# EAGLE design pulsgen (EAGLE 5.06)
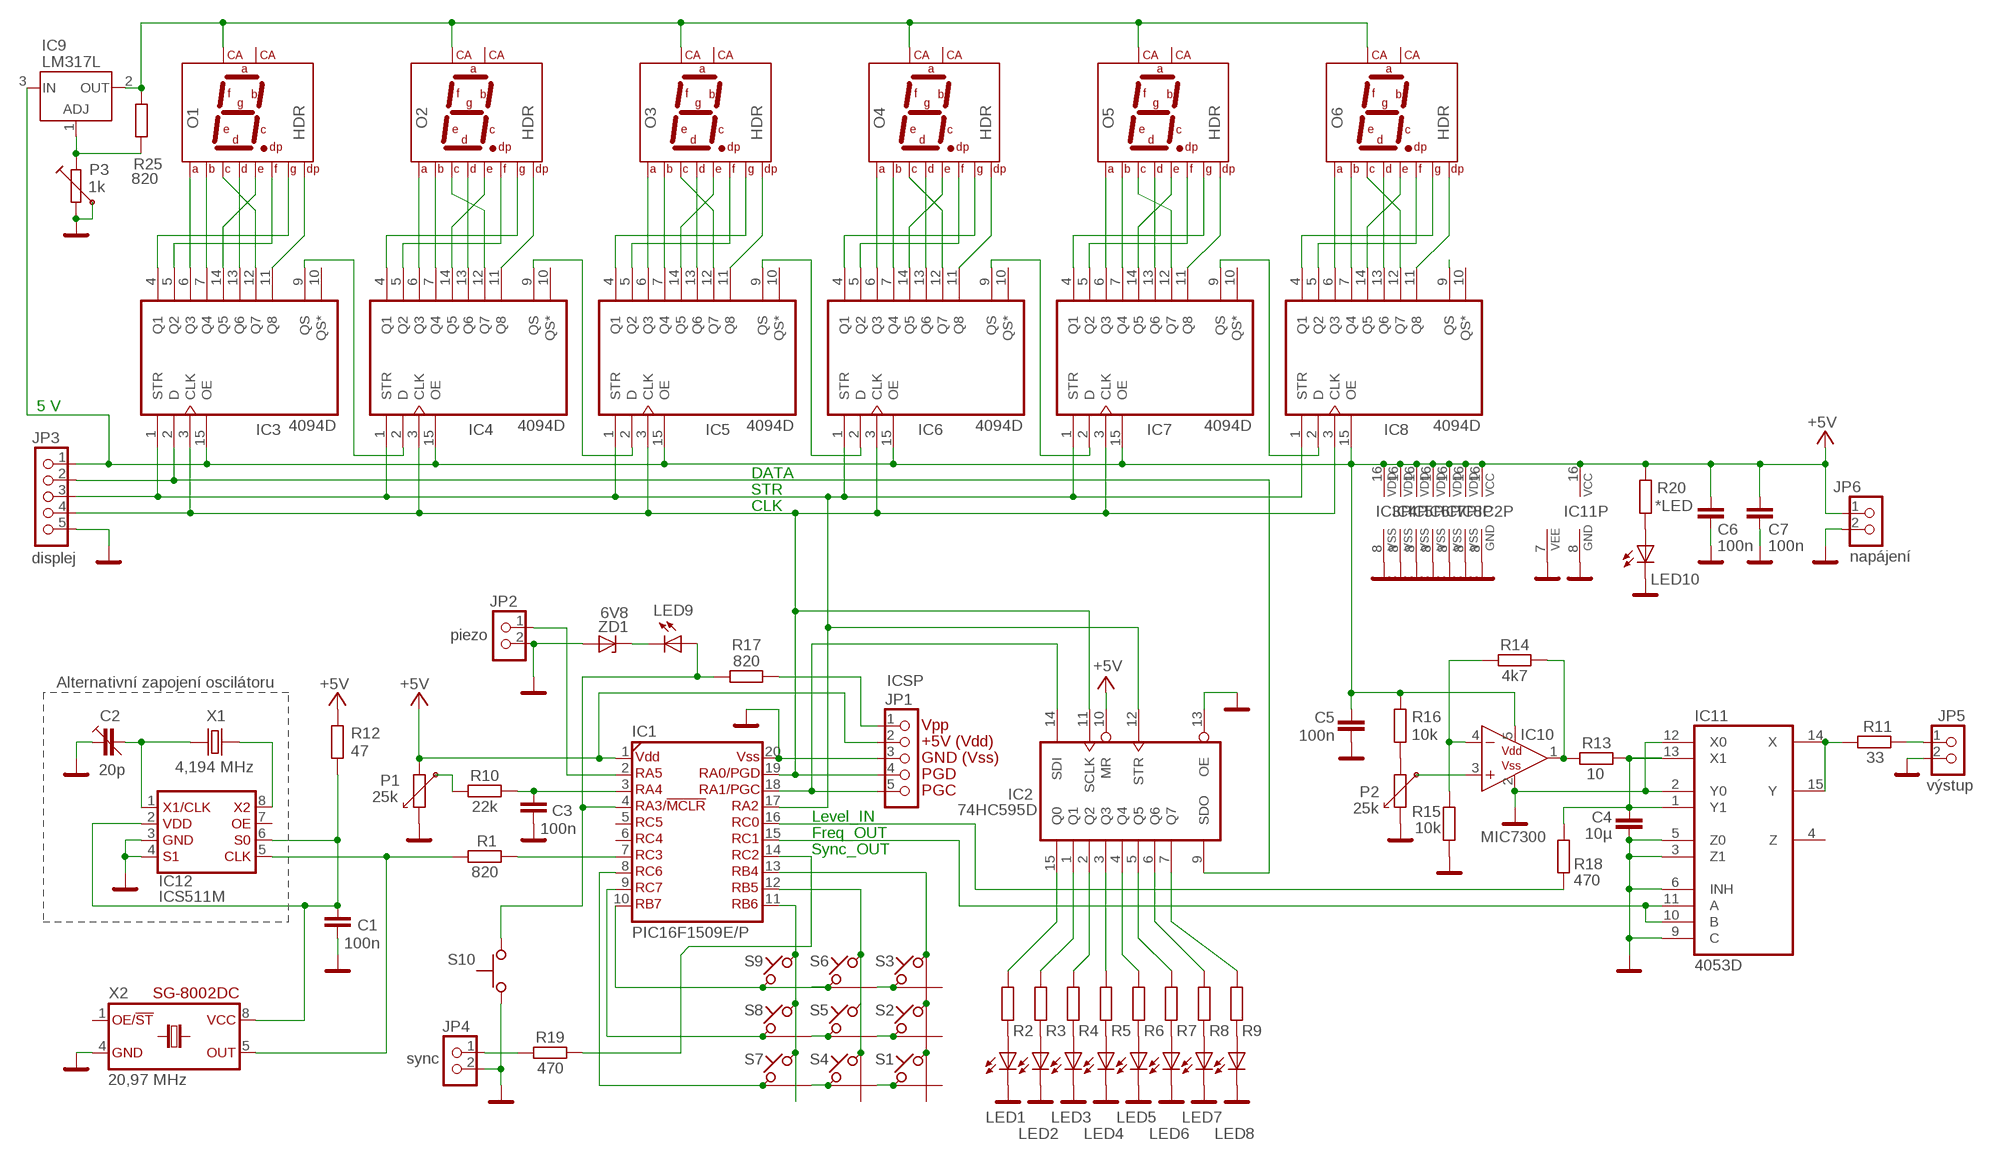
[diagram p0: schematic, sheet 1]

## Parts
C1  100n  CSMD1206_KEMET_REFLOW  [C1206K]
C2  20p  C_TRIMR_JEN_ZNACKA  [2PIN_5MM]
C3  100n  CSMD1206_KEMET_REFLOW  [C1206K]
C4  10µ  CSMD1206_KEMET_REFLOW  [C1206K]
C5  100n  CSMD1206_KEMET_REFLOW  [C1206K]
C6  100n  CSMD1206_KEMET_REFLOW  [C1206K]
C7  100n  CSMD1206_KEMET_REFLOW  [C1206K]
IC1  PIC16F1509E/P  [DIL20]
IC2  74HC595D  74HC595S  [SO16-RN]
IC3  4094D  [SO16-RN]
IC4  4094D  [SO16-RN]
IC5  4094D  [SO16-RN]
IC6  4094D  [SO16-RN]
IC7  4094D  [SO16-RN]
IC8  4094D  [SO16-RN]
IC9  LM317L  [TO92]
IC10  MIC7300  MCP6L01_  [SOT23-5]
IC11  4053D  4053S  [SO16-RN@1]
IC12  ICS511M  ICS511  [SO08-RN]
JP1  ICSP_PIN  [1X05]
JP2  PINHD-1X2  [1X02]
JP3  PINHD-1X5  [1X05]
JP4  PINHD-1X2  [1X02]
JP5  PINHD-1X2  [1X02]
JP6  PINHD-1X2  [1X02]
LED1  LED5MM  [LED5MM]
LED2  LED5MM  [LED5MM]
LED3  LED5MM  [LED5MM]
LED4  LED5MM  [LED5MM]
LED5  LED5MM  [LED5MM]
LED6  LED5MM  [LED5MM]
LED7  LED5MM  [LED5MM]
LED8  LED5MM  [LED5MM]
LED9  LED1206  [SMD1206-LED]
LED10  LED5MM  [LED5MM]
O1  HDR  [HD-A55X]
O2  HDR  [HD-A55X]
O3  HDR  [HD-A55X]
O4  HDR  [HD-A55X]
O5  HDR  [HD-A55X]
O6  HDR  [HD-A55X]
P1  25k  POTENCIOMETR_PC16ML-L  [PC16ML-L]
P2  25k  POTENCIOMETR_PC16ML-L  [PC16ML-L]
P3  1k  R-TRIMRPT6V  [PT6V]
R1  820  REZISTOR_SMD1206_KEMET_REFLOW  [C1206K]
R2  REZISTOR_SMD1206_KEMET_REFLOW  [C1206K]
R3  REZISTOR_SMD1206_KEMET_REFLOW  [C1206K]
R4  REZISTOR_SMD1206_KEMET_REFLOW  [C1206K]
R5  REZISTOR_SMD1206_KEMET_REFLOW  [C1206K]
R6  REZISTOR_SMD1206_KEMET_REFLOW  [C1206K]
R7  REZISTOR_SMD1206_KEMET_REFLOW  [C1206K]
R8  REZISTOR_SMD1206_KEMET_REFLOW  [C1206K]
R9  REZISTOR_SMD1206_KEMET_REFLOW  [C1206K]
R10  22k  REZISTOR_SMD1206_KEMET_REFLOW  [C1206K]
R11  33  REZISTOR_SMD1206_KEMET_REFLOW  [C1206K]
R12  47  REZISTOR_SMD1206_KEMET_REFLOW  [C1206K]
R13  10  REZISTOR_SMD1206_KEMET_REFLOW  [C1206K]
R14  4k7  REZISTOR_SMD1206_KEMET_REFLOW  [C1206K]
R15  10k  REZISTOR_SMD1206_KEMET_REFLOW  [C1206K]
R16  10k  REZISTOR_SMD1206_KEMET_REFLOW  [C1206K]
R17  820  REZISTOR_SMD1206_KEMET_REFLOW  [C1206K]
R18  470  REZISTOR_SMD1206_KEMET_REFLOW  [C1206K]
R19  470  REZISTOR_SMD1206_KEMET_REFLOW  [C1206K]
R20  *LED  REZISTOR_SMD1206_KEMET_REFLOW  [C1206K]
R25  820  REZISTOR_SMD1206_KEMET_REFLOW  [C1206K]
S1  TLACITKO_MATICE_P-B1720  [P-B1720]
S2  TLACITKO_MATICE_P-B1720  [P-B1720]
S3  TLACITKO_MATICE_P-B1720  [P-B1720]
S4  TLACITKO_MATICE_P-B1720  [P-B1720]
S5  TLACITKO_MATICE_P-B1720  [P-B1720]
S6  TLACITKO_MATICE_P-B1720  [P-B1720]
S7  TLACITKO_MATICE_P-B1720  [P-B1720]
S8  TLACITKO_MATICE_P-B1720  [P-B1720]
S9  TLACITKO_MATICE_P-B1720  [P-B1720]
S10  TLACITKOP-B1729  [P-B1729]
X1  4,194 MHz  XTAL_HC49  [XTAL_HC-49]
X2  20,97 MHz  SG-8002DC  [SG-8002DC]
ZD1  6V8  DIODA_ZENER_SOD80  [SOD80-R]

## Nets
+5V: C5.1 C6.1 C7.1 IC1.1(VDD) IC2.10(MR) IC2.16(VCC) IC3.15(OE) IC3.16(VDD) IC4.15(OE) IC4.16(VDD) IC5.15(OE) IC5.16(VDD) IC6.15(OE) IC6.16(VDD) IC7.15(OE) IC7.16(VDD) IC8.15(OE) IC8.16(VDD) IC9.3(IN) IC10.5(VDD) IC11.16(VCC) JP1.2 JP3.1 JP6.1 P1.1 R12.2 R16.1 R20.1
GND: C1.2 C2.P$1 C3.2 C4.2 C5.2 C6.2 C7.2 IC1.20(VSS) IC2.8(GND) IC2.13(OE) IC3.8(VSS) IC4.8(VSS) IC5.8(VSS) IC6.8(VSS) IC7.8(VSS) IC8.8(VSS) IC10.2(VSS) IC11.2(Y0) IC11.3(Z1) IC11.5(Z0) IC11.6(INH) IC11.7(VEE) IC11.8(GND) IC11.9(C) IC11.12(X0) IC12.3(GND) IC12.4(S1) JP1.3 JP2.2 JP3.5 JP4.2 JP5.2 JP6.2 LED1.K(C) LED2.K(C) LED3.K(C) LED4.K(C) LED5.K(C) LED6.K(C) LED7.K(C) LED8.K(C) LED10.K(C) P1.2 P2.2 P3.1 P3.3 R15.2 S10.1 X2.4(GND) ZD1.A
N$1: IC3.4(Q1) O1.10(G)
N$2: IC3.5(Q2) O1.9(F)
N$3: IC3.6(Q3) O1.7(A)
N$4: IC3.7(Q4) O1.6(B)
N$5: IC3.14(Q5) O1.1(E)
N$6: IC3.13(Q6) O1.2(D)
N$7: IC3.12(Q7) O1.4(C)
N$8: IC3.11(Q8) O1.5(DP)
N$9: IC5.4(Q1) O3.10(G)
N$10: IC3.9(QS) IC4.2(D)
N$11: IC9.1(ADJ) P3.2 R25.2
N$12: IC4.9(QS) IC5.2(D)
N$13: IC4.4(Q1) O2.10(G)
N$14: IC4.5(Q2) O2.9(F)
N$15: IC4.6(Q3) O2.7(A)
N$16: IC4.7(Q4) O2.6(B)
N$17: IC4.14(Q5) O2.1(E)
N$18: IC4.13(Q6) O2.2(D)
N$19: IC4.12(Q7) O2.4(C)
N$20: IC4.11(Q8) O2.5(DP)
N$21: LED9.K(C) ZD1.K
N$22: IC1.18(RA1) IC2.14(SDI) JP1.5
N$23: IC8.9(QS)
N$24: IC6.4(Q1) O4.10(G)
N$25: IC6.5(Q2) O4.9(F)
N$26: IC6.6(Q3) O4.7(A)
N$27: IC6.7(Q4) O4.6(B)
N$28: IC6.14(Q5) O4.1(E)
N$29: IC6.13(Q6) O4.2(D)
N$30: IC6.12(Q7) O4.4(C)
N$31: IC6.11(Q8) O4.5(DP)
N$32: IC7.4(Q1) O5.10(G)
N$33: IC5.5(Q2) O3.9(F)
N$34: IC5.6(Q3) O3.7(A)
N$35: IC5.7(Q4) O3.6(B)
N$36: IC5.14(Q5) O3.1(E)
N$37: IC5.13(Q6) O3.2(D)
N$38: IC5.12(Q7) O3.4(C)
N$39: IC5.11(Q8) O3.5(DP)
N$40: IC7.5(Q2) O5.9(F)
N$41: IC2.9(SDO) IC3.2(D) JP3.2
N$42: IC12.5(CLK) R1.1 X2.5(OUT)
N$43: IC1.7(RC3) R1.2
N$44: P1.3 R10.1
N$45: IC7.6(Q3) O5.7(A)
N$46: IC7.7(Q4) O5.6(B)
N$47: IC7.14(Q5) O5.1(E)
N$48: IC7.13(Q6) O5.2(D)
N$49: IC7.12(Q7) O5.4(C)
N$50: IC7.11(Q8) O5.5(DP)
N$51: IC8.4(Q1) O6.10(G)
N$52: IC8.5(Q2) O6.9(F)
N$53: IC8.6(Q3) O6.7(A)
N$54: IC8.7(Q4) O6.6(B)
N$55: IC8.14(Q5) O6.1(E)
N$56: IC8.13(Q6) O6.2(D)
N$57: IC8.12(Q7) O6.4(C)
N$58: IC8.11(Q8) O6.5(DP)
N$59: IC9.2(OUT) O1.3(CA1) O2.3(CA1) O3.3(CA1) O4.3(CA1) O5.3(CA1) O6.3(CA1) R25.1
N$60: JP5.1 R11.2
N$61: C3.1 IC1.3(RA4) R10.2
N$62: IC1.17(RA2) IC2.12(STR) IC3.1(STR) IC4.1(STR) IC5.1(STR) IC6.1(STR) IC7.1(STR) IC8.1(STR) JP3.3
N$63: IC7.9(QS) IC8.2(D)
N$64: IC5.9(QS) IC6.2(D)
N$65: IC1.4(RA3) LED9.A R17.1 S10.2
N$66: IC6.9(QS) IC7.2(D)
N$67: IC12.8(X2) X1.2
N$68: C2.P$2 IC12.1(X1/CLK) X1.1
N$69: S2.2 S3.4
N$70: S1.2 S2.4
N$71: C1.1 IC12.2(VDD) IC12.6(S0) R12.1 X2.8(VCC)
N$72: IC1.10(RB7) S6.1 S9.1 S9.3
N$73: S5.2 S6.4
N$74: S8.2 S9.4
N$75: IC1.9(RC7) S8.1
N$76: IC1.8(RC6) S7.1
N$77: S7.2 S8.4
N$78: IC11.14(X) IC11.15(Y) R11.1
N$79: S3.1 S6.3
N$80: S2.1 S5.3
N$81: IC1.13(RB4) S3.2
N$82: S1.1 S4.3
N$83: JP1.1 R17.2
N$84: S5.1 S8.3
N$85: IC1.11(RB6) S7.4 S9.2
N$86: S4.1 S7.3
N$87: IC10.1(OUT) R13.1 R14.2
N$88: IC2.15(Q0) R2.2
N$89: IC2.1(Q1) R3.2
N$90: IC2.2(Q2) R4.2
N$91: IC2.3(Q3) R5.2
N$92: IC2.4(Q4) R6.2
N$93: IC2.5(Q5) R7.2
N$94: IC2.6(Q6) R8.2
N$95: IC2.7(Q7) R9.2
N$96: LED1.A R2.1
N$97: LED2.A R3.1
N$98: LED3.A R4.1
N$99: LED4.A R5.1
N$100: LED5.A R6.1
N$101: LED6.A R7.1
N$102: LED7.A R8.1
N$103: LED8.A R9.1
N$104: IC1.2(RA5) JP2.1
N$105: P2.1 R16.2
N$106: IC1.15(RC1) IC11.10(B) IC11.11(A)
N$107: IC1.16(RC0) R18.2
N$108: IC1.12(RB5) S4.2 S5.4 S6.2
N$109: IC10.3(+IN) P2.3
N$110: IC10.4(-IN) R14.1 R15.1
N$111: IC1.19(RA0) IC2.11(SCLK) IC3.3(CLK) IC4.3(CLK) IC5.3(CLK) IC6.3(CLK) IC7.3(CLK) IC8.3(CLK) JP1.4 JP3.4
N$115: JP4.1 R19.1
N$116: C4.1 IC11.1(Y1) IC11.13(X1) R13.2 R18.1
N$117: IC1.14(RC2) R19.2
N$118: LED10.A R20.2
Unconnected: IC1.5(RC5) IC1.6(RC4) IC3.10(QS*) IC4.10(QS*) IC5.10(QS*) IC6.10(QS*) IC7.10(QS*) IC8.10(QS*) IC11.4(Z) IC12.7(OE) O1.8(CA2) O2.8(CA2) O3.8(CA2) O4.8(CA2) O5.8(CA2) O6.8(CA2) S1.3 S1.4 S2.3 S3.3 S4.4 S10.3 S10.4 X2.1(OE/!ST)

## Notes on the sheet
- 5 V
- DATA
- STR
- CLK
- displej | napájení
- piezo
- Alternativní zapojení oscilátoru | ICSP
- výstup
- Level_IN
- Freq_OUT
- Sync_OUT
- sync

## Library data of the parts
C1 C3-C7 = #bcs7d:C: Kondenzatory, keramicke a foliove
C2 = #bcs7d:C_TRIMR_JEN_ZNACKA: C trimr jen znacka
IC1 = #bcs-ic1:PIC16F1509
IC2 = 74xx-bcs:74*595: 8-bit SHIFT REGISTER, output latch
IC3-IC8 = 40xx_bcs:4094: 8-stage SHIFT/STORE REGISTER, tri-state
IC9 = #bcs-ic1:LM317L
IC10 = #bcs-ic1:MCP6L01: 5 pin OA MCP6L01
IC11 = 40xx_bcs:4053: Triple 2-channel ANALOG MULTIPLEXER
IC12 = #bcs-ic1:ICS511
JP1 = #bcs-ic1:ICSP_PIN: PIN HEADER
JP2 JP4-JP6 = #bcs_pinhead:PINHD-1X2: PIN HEADER
JP3 = #bcs_pinhead:PINHD-1X5: PIN HEADER
LED1-LED10 = #bcs7d:LED: LED
O1-O6 = #bcs-ic1:HD: 7 segment display
P1 P2 = #bcs7d:POTENCIOMETR
P3 = #bcs7d:R-TRIMR
R1-R20 R25 = #bcs7d:REZISTOR_
S1-S9 = #bcs7d:TLACITKO_MATICE: Tlacitko 4 piny pro maticové klávesnice
S10 = #bcs7d:TLACITKO
X1 = #bcs7d:XTAL
X2 = #bcs-ic1:SG-8002DC: EPSON Programmable oscillator
ZD1 = #bcs7d:DIODA_ZENER

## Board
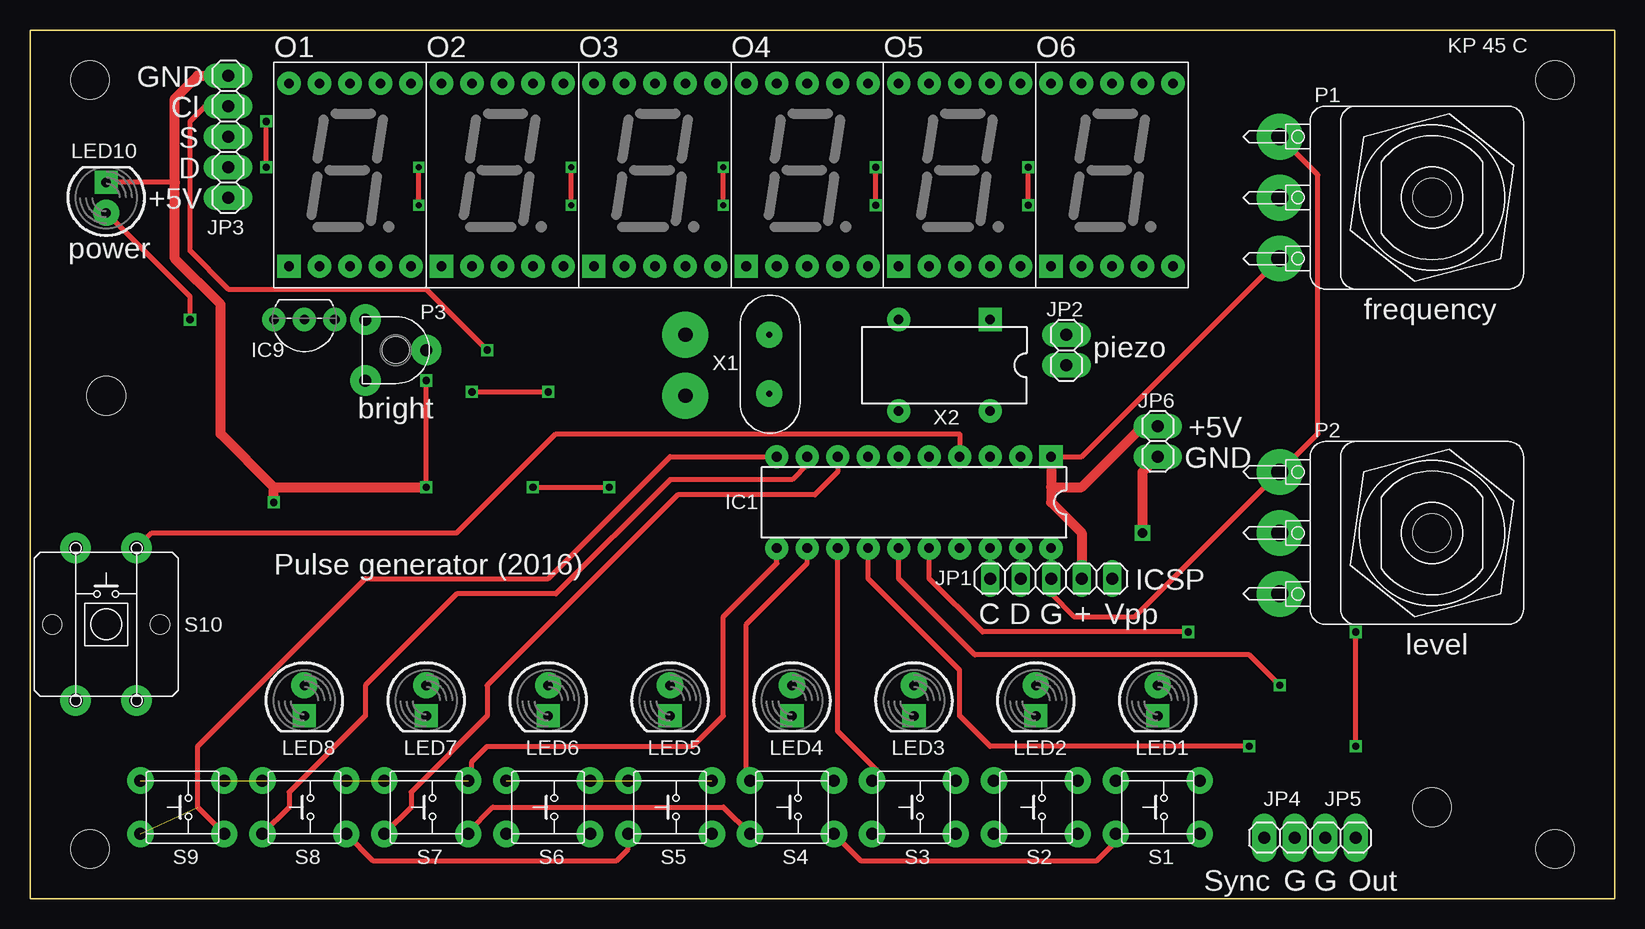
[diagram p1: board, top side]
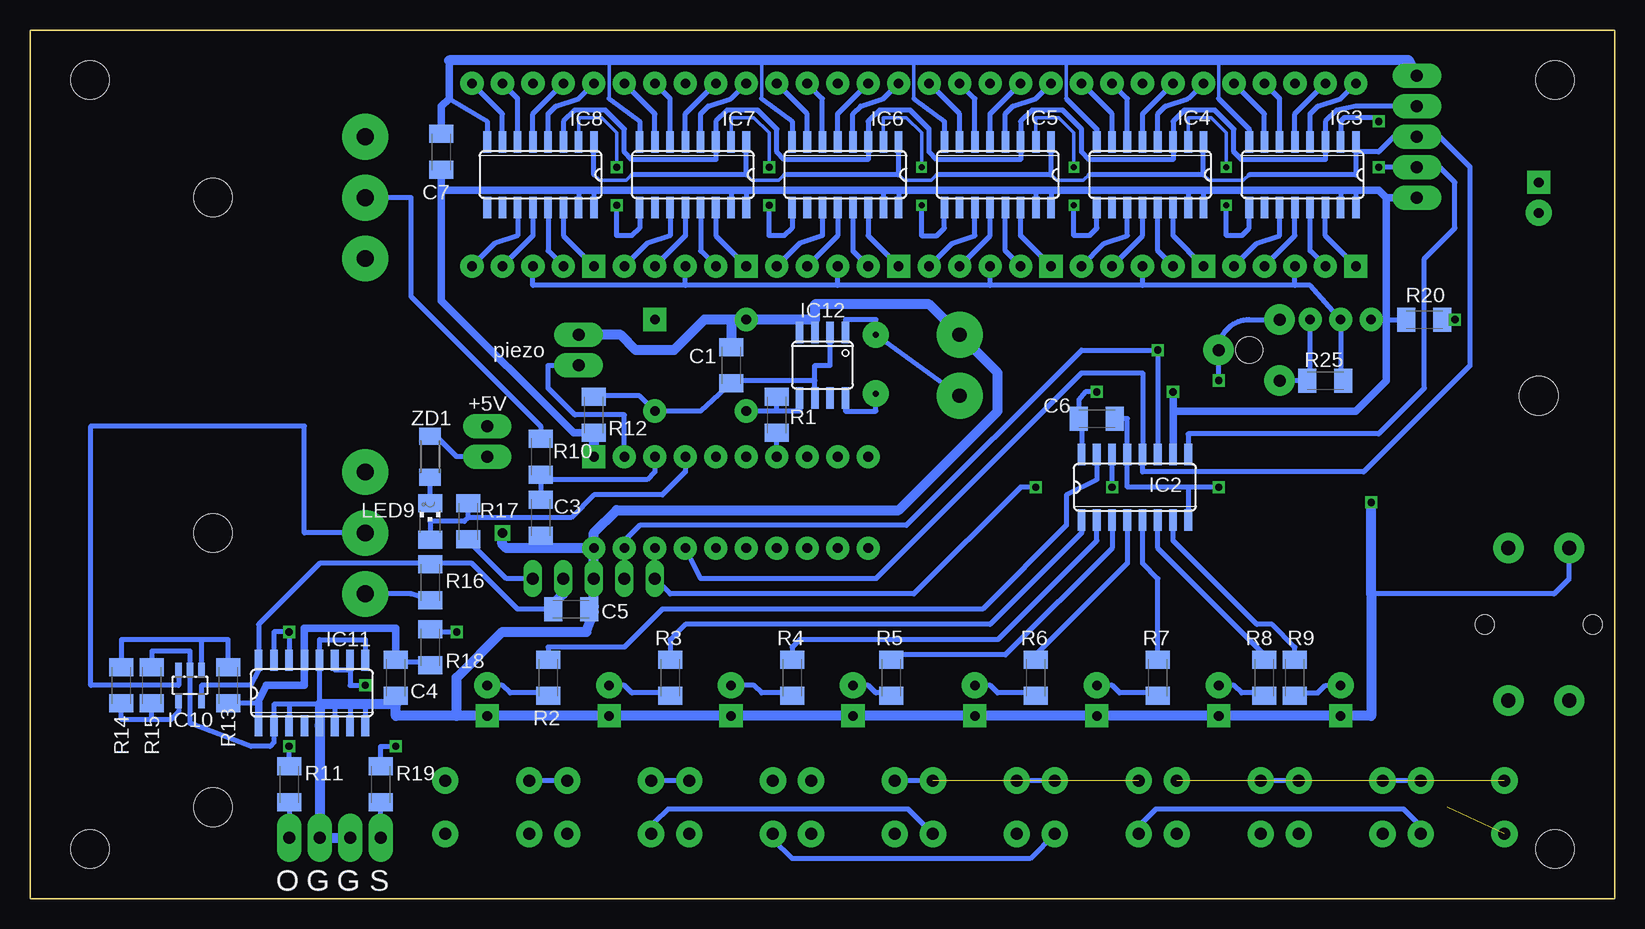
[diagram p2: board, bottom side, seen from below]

Size 132.08 x 72.39 mm. Coordinates in mm from the lower left corner, seen from the top.
Copper layers (1*16): Top 0.035mm / dielectric 1.5mm / Bottom 0.035mm
Design rules "default": minimum track width 10mil, minimum drill 24mil, track to track 8mil, track to pad 8mil, pad to pad 8mil, via to via 8mil, smd to smd 8mil, copper to edge 40mil, drill to drill 8mil, minimum pad ring 10mil, minimum via ring 8mil, stop-mask expansion 4mil, vias tented up to drill 0mil, thermal gap 10mil
Holes 3.2 mm at 116.84,7.62 116.84,30.48 116.84,58.42 6.35,41.91
Holes 2.2 mm at 30.48,45.72

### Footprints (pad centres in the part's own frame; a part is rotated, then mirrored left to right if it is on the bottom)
C1206K = smd 1.5 x 2: 1 -1.5,0; 2 1.5,0
2PIN_5MM = drill 1.2 pad 3.81 round: P$1 -2.54,0; P$2 2.54,0
DIL20 = drill 0.8 pad 1.93 square: 1 -11.43,-3.81 | drill 0.8 pad 1.93 round: 2 -8.89,-3.81; 3 -6.35,-3.81; 4 -3.81,-3.81; 5 -1.27,-3.81; 6 1.27,-3.81; 7 3.81,-3.81; 8 6.35,-3.81; 9 8.89,-3.81; 10 11.43,-3.81; 11 11.43,3.81; 12 8.89,3.81; 13 6.35,3.81; 14 3.81,3.81; 15 1.27,3.81; 16 -1.27,3.81; 17 -3.81,3.81; 18 -6.35,3.81; 19 -8.89,3.81; 20 -11.43,3.81
SO16-RN = smd 0.635 x 1.778: 1 -3.81,-2.731; 2 -2.54,-2.731; 3 -1.27,-2.731; 4 0,-2.731; 5 1.27,-2.731; 6 2.54,-2.731; 7 3.81,-2.731; 8 5.08,-2.731; 9 5.08,2.731; 10 3.81,2.731; 11 2.54,2.731; 12 1.27,2.731; 13 0,2.731; 14 -1.27,2.731; 15 -2.54,2.731; 16 -3.81,2.731
SO16-RN' = smd 0.635 x 1.778: 1 -4.445,-2.731; 2 -3.175,-2.731; 3 -1.905,-2.731; 4 -0.635,-2.731; 5 0.635,-2.731; 6 1.905,-2.731; 7 3.175,-2.731; 8 4.445,-2.731; 9 4.445,2.731; 10 3.175,2.731; 11 1.905,2.731; 12 0.635,2.731; 13 -0.635,2.731; 14 -1.905,2.731; 15 -3.175,2.731; 16 -4.445,2.731
TO92 = drill 0.8 pad 1.93 round: 1 -2.54,0; 2 0,0; 3 2.54,0
SOT23-5 = smd 0.55 x 1.2: 1 -0.95,-1.3; 2 0,-1.3; 3 0.95,-1.3; 4 0.95,1.3; 5 -0.95,1.3
SO16-RN@1 = smd 0.635 x 1.778: 1 -3.81,-2.731; 2 -2.54,-2.731; 3 -1.27,-2.731; 4 0,-2.731; 5 1.27,-2.731; 6 2.54,-2.731; 7 3.81,-2.731; 8 5.08,-2.731; 9 5.08,2.731; 10 3.81,2.731; 11 2.54,2.731; 12 1.27,2.731; 13 0,2.731; 14 -1.27,2.731; 15 -2.54,2.731; 16 -3.81,2.731
SO08-RN = smd 0.635 x 1.778: 1 -1.905,-2.731; 2 -0.635,-2.731; 3 0.635,-2.731; 4 1.905,-2.731; 5 1.905,2.731; 6 0.635,2.731; 7 -0.635,2.731; 8 -1.905,2.731
1X05 = drill 1 pad 1.524 long: 1 -5.08,0; 2 -2.54,0; 3 0,0; 4 2.54,0; 5 5.08,0
1X02 = drill 1 pad 2.032 long: 1 -1.27,0; 2 1.27,0
1X05' = drill 1 pad 2.032 long: 1 -5.08,0; 2 -2.54,0; 3 0,0; 4 2.54,0; 5 5.08,0
LED5MM = drill 0.8 pad 2.184 round: A -1.27,0 | drill 0.8 pad 1.93 square: K 1.27,0
SMD1206-LED = smd 1.5 x 2: A -1.511,0; K 1.511,0
HD-A55X = drill 0.8 pad 1.93 square: 1 0,0 | drill 0.8 pad 1.93 round: 2 2.54,0; 3 5.08,0; 4 7.62,0; 5 10.16,0; 6 10.16,15.24; 7 7.62,15.24; 8 5.08,15.24; 9 2.54,15.24; 10 0,15.24
PC16ML-L = drill 1.4 pad 3.81 round: 1 -5.08,12.7; 2 5.08,12.7; 3 0,12.7
PT6V = drill 1 pad 2.54 round: 1 -2.54,-2.54; 2 2.54,-2.54; 3 0,2.54
P-B1720 = drill 1 pad 2.184 round: 1 -3.493,-2.223; 2 -3.493,2.223; 3 3.493,-2.223; 4 3.493,2.223
P-B1729 = drill 1.2 pad 2.54 round: 1 -6.35,-2.54; 2 -6.35,2.54; 3 6.35,-2.54; 4 6.35,2.54 | hole 1.6: 0,4.5; 0,-4.5
KRABICKA_KP_45_C = hole 3.2: 4.991,4.128; 4.991,68.237; 127.089,68.237; 127.089,4.128
XTAL_HC-49 = drill 0.5 pad 2.184 round: 1 0,0; 2 4.9,0
SG-8002DC = drill 0.8 pad 1.93 square: 1 -3.81,-3.81 | drill 0.8 pad 1.93 round: 4 3.81,-3.81; 5 3.81,3.81; 8 -3.81,3.81
SOD80-R = smd 1.397 x 1.778: A 1.714,0; K -1.714,0

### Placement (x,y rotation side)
C1  73.66,44.45 90 bottom
C2  54.61,44.45 270 top
C3  89.53,31.75 270 bottom
C4  101.6,18.41 270 bottom
C5  87,24.13 0 bottom
C6  43.18,40.01 0 bottom
C7  97.79,62.23 90 bottom
IC1  73.66,33.02 180 top
IC2  40.64,34.29 0 bottom
IC3  4094D  [SO16-RN']  26.04,60.33 180 bottom
IC4  4094D  [SO16-RN']  38.73,60.33 180 bottom
IC5  4094D  [SO16-RN']  51.44,60.33 180 bottom
IC6  4094D  [SO16-RN']  64.14,60.33 180 bottom
IC7  4094D  [SO16-RN']  76.83,60.33 180 bottom
IC8  4094D  [SO16-RN']  89.53,60.33 180 bottom
IC9  22.86,48.26 180 top
IC10  118.75,17.78 180 bottom
IC11  109.22,17.14 0 bottom
IC12  66.04,44.45 180 bottom
JP1  85.09,26.67 180 top
JP2  86.36,45.72 90 top
JP3  [1X05']  16.51,63.5 90 top
JP4  104.14,5.08 0 top
JP5  109.22,5.08 180 top
JP6  93.98,38.1 270 top
LED1  93.98,16.51 270 top
LED2  83.82,16.51 270 top
LED3  73.66,16.51 270 top
LED4  63.5,16.51 270 top
LED5  53.34,16.51 270 top
LED6  43.18,16.51 270 top
LED7  33.02,16.51 270 top
LED8  22.86,16.51 270 top
LED9  98.74,31.43 90 bottom
LED10  6.35,58.42 90 top
O1  21.59,52.7 0 top
O2  34.29,52.7 0 top
O3  46.99,52.7 0 top
O4  59.69,52.7 0 top
O5  72.39,52.7 0 top
O6  85.09,52.7 0 top
P1  116.84,58.42 90 top
P2  116.84,30.48 90 top
P3  30.48,45.72 270 top
R1  69.85,40.32 270 bottom
R2  88.9,18.41 90 bottom
R3  78.74,18.41 90 bottom
R4  68.58,18.41 90 bottom
R5  60.33,18.41 90 bottom
R6  48.26,18.41 90 bottom
R7  38.1,18.41 90 bottom
R8  29.21,18.41 90 bottom
R9  26.67,18.41 90 bottom
R10  89.53,36.83 270 bottom
R11  110.49,9.53 270 bottom
R12  85.09,40.32 270 bottom
R13  115.57,17.78 270 bottom
R14  124.46,17.78 90 bottom
R15  121.92,17.78 90 bottom
R16  98.74,26.35 270 bottom
R17  95.57,31.43 270 bottom
R18  98.74,20.95 90 bottom
R19  102.87,9.53 90 bottom
R20  15.88,48.26 0 bottom
R25  24.13,43.18 180 bottom
S1  93.98,7.62 0 top
S2  83.82,7.62 0 top
S3  73.66,7.62 0 top
S4  63.5,7.62 0 top
S5  53.34,7.62 0 top
S6  43.18,7.62 0 top
S7  33.02,7.62 0 top
S8  22.86,7.62 0 top
S9  12.7,7.62 0 top
S10  6.35,22.86 270 top
U$1  [KRABICKA_KP_45_C]  0,0 0 top
X1  61.59,46.99 270 top
X2  76.2,44.45 180 top
ZD1  98.74,36.83 90 bottom

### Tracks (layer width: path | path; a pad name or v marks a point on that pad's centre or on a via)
+5V  (via drill 0.6)
  Top 0.406: v36.83,42.23 v43.18,42.23 | P1.1 87.63,36.83 IC1.1
  Top 0.813: JP1.2 87.63,30.48 85.09,33.02 85.09,34.29 | IC1.1 85.09,34.29 | JP6.1 92.71,39.37 87.63,34.29 85.09,34.29
  Bottom 0.406: 34.29,59.05 IC4.16 | 35.56,59.05 IC4.15 | 46.99,59.05 IC5.16 | 48.26,59.05 IC5.15 | 59.69,59.05 IC6.16 | 86.36,59.05 IC8.15 | 60.96,59.05 IC6.15 | 72.39,59.05 IC7.16 | 73.66,59.05 IC7.15 | 85.09,59.05 IC8.16 | IC10.5 117.8,17.78 113.67,17.78 113.03,19.05 IC11.16 113.03,22.86 107.95,27.94 99.06,27.94 | 99.06,27.94 R16.1 | 99.06,27.94 95.25,27.94 91.44,24.13 C5.1 88.27,24.36 88.27,24.77 | IC2.16 44.45,40.01 C6.1 44.68,41.59 44.13,42.23 v43.18,42.23 | 19.05,48.26 R20.1 | 21.59,59.05 IC3.16 | 22.86,59.05 IC3.15
  Bottom 0.61: 97.79,59.05 86.36,59.05 85.09,59.05 73.66,59.05 72.39,59.05 60.96,59.05 59.69,59.05 48.26,59.05 46.99,59.05 35.56,59.05 34.29,59.05 22.86,59.05 21.59,59.05 19.68,59.05 19.05,58.42 | 36.83,40.64 IC2.10 | 97.79,59.05 97.79,49.85 86.77,38.82 R12.2 | 19.05,58.42 JP3.1 | 36.83,40.64 21.59,40.64 19.05,43.18 19.05,48.26 | 19.05,48.26 19.05,58.42 | 19.05,48.26 IC9.3 | 36.83,40.64 v36.83,42.23 | 97.79,59.05 C7.1
  Bottom 0.813: R12.2 IC1.1 | JP1.2 87.63,25.4 88.27,24.77
GND  (via drill 0.6, 0.8 pad 1.27)
  Top 0.406: v33.02,34.29 v33.02,43.18 | P1.2 107.31,60.33 107.31,38.73 P2.2 92.08,23.5 87,23.5 85.09,25.4 JP1.3 | 12.06,59.69 LED10.K
  Top 0.813: 20.32,34.29 v33.02,34.29 | 20.32,34.29 15.88,38.73 15.88,49.53 12.06,53.34 12.06,59.69 12.06,66.67 13.97,68.58 JP3.5 | v20.32,33.02 20.32,34.29 | JP6.2 92.71,35.56 v92.71,30.48
  Bottom 0.305: 33.02,69.85 33.02,66.67 | 45.72,69.85 45.72,66.67 | 58.42,69.85 58.42,66.67 | 71.12,69.85 71.12,66.67 | 83.82,69.85 83.82,66.67
  Bottom 0.406: IC3.8 30.48,64.14 33.02,66.67 | IC4.8 43.18,64.14 45.72,66.67 | 58.42,66.67 55.88,64.77 IC5.8 | IC6.8 68.58,64.77 71.12,66.67 | IC7.8 81.28,64.77 83.82,66.67 | IC8.8 93.98,64.77 97.16,66.67 | 110.49,16.19 111.76,16.19 IC11.2 111.76,13.02 112.08,12.7 113.67,12.7 118.75,14.61 IC10.2 118.75,20.64 121.92,20.64 R15.2 | 110.49,16.19 107.95,16.19 IC11.12 107.95,21.59 104.14,21.59 IC11.9 | 104.14,16.19 IC11.8 | 106.68,16.19 IC11.6 | 110.49,16.19 IC11.3 | 105.41,16.19 IC11.7 | C4.2 101.6,16.51 | 66.67,48.26 IC12.3 | 67.94,48.26 IC12.4 | v33.02,34.29 35.56,34.29 | 35.56,34.29 40.64,34.29 IC2.13 40.64,40.01 C6.2 | P3.1 30.48,48.26 arc-90 P3.3 v33.02,43.18 | 89.53,29.21 C3.2 | 85.09,24.36 C5.2 85.09,23.9 | 35.56,34.29 IC2.8 | S10.1 3.81,26.67 5.08,25.4 20.32,25.4 | ZD1.A 98.23,38.54 96.52,36.83 JP6.2
  Bottom 0.61: 97.16,69.85 97.16,66.67 97.79,66.04 C7.2
  Bottom 0.813: IC1.20 JP1.3 85.09,24.36 | 73.66,48.26 X2.4 67.94,48.26 66.67,48.26 66.67,49.53 57.15,49.53 C2.P$1 51.44,43.81 51.44,40.64 59.69,32.38 83.19,32.38 85.09,30.48 IC1.20 | 73.66,48.26 C1.2 | 97.16,69.85 83.82,69.85 71.12,69.85 58.42,69.85 45.72,69.85 33.02,69.85 17.14,69.85 JP3.5 | 101.6,16.51 101.6,16.19 104.14,16.19 105.41,16.19 106.68,16.19 107.95,16.19 IC11.5 JP5.2 JP4.2 | 96.52,15.24 96.52,18.41 92.71,22.23 85.72,22.23 85.09,23.9 | 96.52,15.24 LED1.K LED2.K LED3.K LED4.K LED5.K LED6.K LED7.K LED8.K 20.32,15.24 20.32,25.4 v20.32,33.02 | 96.52,15.24 101.6,15.24 C4.2 | JP2.2 82.87,46.99 81.6,45.72 78.42,45.72 75.88,48.26 73.66,48.26 | IC1.20 89.53,29.21 92.39,29.21 92.71,29.53 v92.71,30.48
N$1
  Bottom 0.406: IC3.4 25.4,65.41 24.77,66.04 22.86,66.67 O1.10
N$2
  Bottom 0.406: IC3.5 26.67,65.41 O1.9
N$3
  Bottom 0.406: IC3.6 27.94,66.67 O1.7
N$4
  Bottom 0.406: IC3.7 29.21,65.41 O1.6
N$5
  Bottom 0.406: IC3.14 24.13,55.24 O1.1
N$6
  Bottom 0.406: IC3.13 25.4,53.98 O1.2
N$7
  Bottom 0.406: IC3.12 26.67,55.24 O1.4
N$8
  Bottom 0.406: IC3.11 27.94,55.24 29.84,54.61 O1.5
N$9
  Bottom 0.406: IC5.4 50.8,65.41 50.16,66.04 48.26,66.67 O3.10
N$10  (via drill 0.5)
  Top 0.406: v32.38,57.78 v32.38,60.96
  Bottom 0.305: v32.38,60.96 32.38,63.82 33.66,65.09 35.56,65.09 IC4.2
  Bottom 0.406: v32.38,57.78 32.38,55.24 31.11,55.24 30.48,55.88 IC3.9
N$11
  Bottom 0.406: IC9.1 25.4,43.18 R25.2 P3.2
N$12  (via drill 0.5)
  Top 0.406: v45.09,57.78 v45.09,60.96
  Bottom 0.305: v45.09,60.96 45.09,63.82 46.35,65.09 48.26,65.09 IC5.2
  Bottom 0.406: v45.09,57.78 45.09,55.24 43.81,55.24 43.18,55.88 IC4.9
N$13
  Bottom 0.406: IC4.4 38.1,65.41 37.47,66.04 35.56,66.67 O2.10
N$14
  Bottom 0.406: IC4.5 39.37,65.41 O2.9
N$15
  Bottom 0.406: IC4.6 40.64,66.67 O2.7
N$16
  Bottom 0.406: IC4.7 41.91,65.41 O2.6
N$17
  Bottom 0.406: IC4.14 36.83,55.24 O2.1
N$18
  Bottom 0.406: IC4.13 38.1,53.98 O2.2
N$19
  Bottom 0.406: IC4.12 39.37,55.24 O2.4
N$20
  Bottom 0.406: IC4.11 40.64,55.24 42.55,54.61 O2.5
N$21
  Bottom 0.406: LED9.K ZD1.K
N$22  (via drill 0.6)
  Top 0.406: v41.91,34.29 v48.26,34.29
  Bottom 0.406: IC1.18 JP1.5 78.74,25.4 58.42,25.4 49.53,34.29 v48.26,34.29 | v41.91,34.29 IC2.14
N$24
  Bottom 0.406: IC6.4 63.5,65.41 62.87,66.04 60.96,66.67 O4.10
N$25
  Bottom 0.406: IC6.5 64.77,65.41 O4.9
N$26
  Bottom 0.406: IC6.6 66.04,66.67 O4.7
N$27
  Bottom 0.406: IC6.7 67.31,65.41 O4.6
N$28
  Bottom 0.406: IC6.14 62.23,55.24 O4.1
N$29
  Bottom 0.406: IC6.13 63.5,53.98 O4.2
N$30
  Bottom 0.406: IC6.12 64.77,55.24 O4.4
N$31
  Bottom 0.406: IC6.11 66.04,55.24 67.94,54.61 O4.5
N$32
  Bottom 0.406: IC7.4 76.2,65.41 75.56,66.04 73.66,66.67 O5.10
N$33
  Bottom 0.406: IC5.5 52.07,65.41 O3.9
N$34
  Bottom 0.406: IC5.6 53.34,66.67 O3.7
N$35
  Bottom 0.406: IC5.7 54.61,65.41 O3.6
N$36
  Bottom 0.406: IC5.14 49.53,55.24 O3.1
N$37
  Bottom 0.406: IC5.13 50.8,53.98 O3.2
N$38
  Bottom 0.406: IC5.12 52.07,55.24 O3.4
N$39
  Bottom 0.406: IC5.11 53.34,55.24 55.24,54.61 O3.5
N$40
  Bottom 0.406: IC7.5 77.47,65.41 O5.9
N$41  (via drill 0.6)
  Top 0.406: v19.68,60.96 v19.68,64.77
  Bottom 0.406: IC2.9 35.56,38.73 19.68,38.73 15.88,42.55 15.88,53.34 13.34,55.88 13.34,59.69 14.61,60.96 JP3.2 v19.68,60.96 | v19.68,64.77 20,65.09 22.54,65.09 22.86,64.77 IC3.2
N$42
  Bottom 0.406: 69.85,40.64 67.94,40.64 IC12.5 | 69.85,40.64 X2.5 | 69.85,40.64 R1.1
N$43
  Bottom 0.406: IC1.7 R1.2
N$44
  Bottom 0.406: P1.3 100.33,58.42 100.33,50.16 89.53,39.37 R10.1
N$45
  Bottom 0.406: IC7.6 78.74,66.67 O5.7
N$46
  Bottom 0.406: IC7.7 80.01,65.41 O5.6
N$47
  Bottom 0.406: IC7.14 74.93,55.24 O5.1
N$48
  Bottom 0.406: IC7.13 76.2,53.98 O5.2
N$49
  Bottom 0.406: IC7.12 77.47,55.24 O5.4
N$50
  Bottom 0.406: IC7.11 78.74,55.24 80.64,54.61 O5.5
N$51
  Bottom 0.406: IC8.4 88.9,65.41 88.27,66.04 86.36,66.67 O6.10
N$52
  Bottom 0.406: IC8.5 90.17,65.41 O6.9
N$53
  Bottom 0.406: IC8.6 91.44,66.67 O6.7
N$54
  Bottom 0.406: IC8.7 92.71,65.41 O6.6
N$55
  Bottom 0.406: IC8.14 87.63,55.24 O6.1
N$56
  Bottom 0.406: IC8.13 88.9,53.98 O6.2
N$57
  Bottom 0.406: IC8.12 90.17,55.24 O6.4
N$58
  Bottom 0.406: IC8.11 91.44,55.24 93.34,54.61 O6.5
N$59
  Bottom 0.406: 26.67,51.12 39.37,51.12 | 39.37,51.12 52.07,51.12 | 26.67,51.12 O1.3 | 39.37,51.12 O2.3 | 52.07,51.12 O3.3 | 52.07,51.12 64.77,51.12 | 64.77,51.12 77.47,51.12 | 77.47,51.12 90.17,51.12 O6.3 | 77.47,51.12 O5.3 | 64.77,51.12 O4.3 | 26.67,51.12 25.4,51.12 IC9.2 22.86,43.18 R25.1
N$60
  Bottom 0.406: R11.2 JP5.1
N$61
  Bottom 0.406: IC1.3 80.01,35.56 80.64,34.92 89.53,34.92 | 89.53,34.92 R10.2 | 89.53,34.92 C3.1
N$62
  Bottom 0.305: 30.48,60.33 30.96,59.85 33.81,59.85 34.29,60.33 | 46.99,60.33 46.51,59.85 44.29,59.85 43.81,60.33 | 56.52,60.33 56.99,59.85 59.21,59.85 59.69,60.33 | 69.22,60.33 69.69,59.85 71.91,59.85 72.39,60.33 | 81.92,60.33 82.39,59.85 84.61,59.85 85.09,60.33
  Bottom 0.406: 21.59,62.23 21.59,60.33 30.48,60.33 | 21.59,62.23 IC3.1 | IC4.1 34.29,60.33 43.81,60.33 | IC5.1 46.99,60.33 56.52,60.33 | IC1.17 76.2,26.67 61.59,26.67 44.45,43.81 39.37,43.81 IC2.12 39.37,35.56 20.95,35.56 12.06,44.45 12.06,60.96 14.61,63.5 JP3.3 18.41,63.5 19.68,62.23 21.59,62.23 | 69.22,60.33 59.69,60.33 IC6.1 | 81.92,60.33 72.39,60.33 IC7.1 | 85.09,60.33 IC8.1
N$63  (via drill 0.6)
  Top 0.406: v83.19,57.78 v83.19,60.96
  Bottom 0.305: v83.19,60.96 83.19,63.82 84.45,65.09 86.36,65.09 IC8.2
  Bottom 0.406: IC7.9 81.28,55.88 81.92,55.24 83.19,55.24 v83.19,57.78
N$64  (via drill 0.5)
  Top 0.406: v57.78,57.78 v57.78,60.96
  Bottom 0.305: IC6.2 60.96,65.09 59.05,65.09 57.78,63.82 v57.78,60.96
  Bottom 0.406: IC5.9 55.88,55.88 56.52,55.24 57.78,55.24 v57.78,57.78
N$65
  Top 0.406: S10.2 10.16,30.48 35.56,30.48 43.81,38.73 77.47,38.73 IC1.4
  Bottom 0.406: IC1.4 77.47,35.56 79.38,33.66 85.09,33.66 87,31.75 95.57,31.75 | 95.57,31.75 R17.1 | 95.57,31.75 95.89,31.43 98.74,31.43 LED9.A
N$66  (via drill 0.6)
  Top 0.406: v70.48,57.78 v70.48,60.96
  Bottom 0.305: v70.48,60.96 70.48,63.82 71.75,65.09 73.66,65.09 IC7.2
  Bottom 0.406: IC6.9 68.58,55.88 69.22,55.24 70.48,55.24 v70.48,57.78
N$67
  Bottom 0.406: IC12.8 64.14,40.64 61.59,40.64 X1.2
N$68
  Bottom 0.406: IC12.1 64.14,48.26 61.59,48.26 X1.1 C2.P$2
N$69
  Bottom 0.406: S3.4 S2.2
N$70
  Bottom 0.406: S2.4 S1.2
N$71
  Bottom 0.406: 85.09,41.91 R12.1 85.09,41.27 84.45,41.91 81.28,41.91 X2.8 76.2,40.64 C1.1 73.43,43.18 66.67,43.18 | IC12.2 65.41,44.45 66.67,44.45 66.67,43.18 | IC12.6 66.67,43.18
N$72  (1 unrouted)
  Top 0.406: IC1.10 53.34,36.83 43.18,26.67 27.94,26.67 13.97,12.7 13.97,7.62 S9.3
  Bottom 0.406: S6.1 39.69,6.03 38.26,7.46 17.62,7.46 16.51,6.35 16.51,5.71 S9.3
N$73
  Bottom 0.406: S6.4 S5.2
N$74
  Bottom 0.406: S9.4 S8.2
N$75
  Top 0.406: IC1.9 64.77,36.2 63.5,34.92 53.34,34.92 43.81,25.4 35.56,25.4 27.94,17.78 27.94,15.24 21.59,8.89 21.59,7.62 S8.1
N$76
  Top 0.406: IC1.8 67.31,35.56 65.41,33.66 53.98,33.66 38.1,17.78 38.1,15.24 31.75,8.89 31.75,7.62 S7.1
N$77
  Bottom 0.406: S8.4 S7.2
N$78  (via drill 0.6)
  Top 0.406: v110.49,12.7 v110.49,22.23
  Bottom 0.406: R11.1 v110.49,12.7 | IC11.14 v110.49,22.23 111.76,22.23 IC11.15
N$79
  Bottom 0.406: S6.3 48.74,3.33 68.58,3.33 70.17,4.92 S3.1
N$80
  Bottom 0.406: S5.3 58.9,7.46 63.66,7.46 78.9,7.46 80.01,6.35 80.01,5.71 S2.1
N$81
  Top 0.406: S3.2 70.48,10.16 70.48,10.79 67.31,13.97 IC1.13
N$82
  Top 0.406: S4.3 69.22,3.17 88.9,3.17 90.49,4.76 S1.1
N$83
  Bottom 0.406: JP1.1 92.39,26.67 95.57,29.84 R17.2
N$84
  Top 0.406: S8.3 28.57,3.17 48.9,3.17 49.85,4.13 S5.1
N$85  (1 unrouted)
  Top 0.406: S7.4 36.83,10.16 36.83,11.43 38.1,12.7 55.24,12.7 57.78,15.24 57.78,23.5 62.23,27.94 IC1.11
N$86
  Top 0.406: S7.3 36.51,5.56 38.58,7.62 57.78,7.62 S4.1
N$87
  Bottom 0.406: R14.2 124.46,21.59 117.8,21.59 | 117.8,21.59 IC10.1 | R13.1 115.57,21.59 117.8,21.59
N$88
  Bottom 0.406: IC2.15 43.18,34.92 45.72,33.66 45.72,31.11 52.7,24.13 79.38,24.13 82.55,20.95 88.9,20.95 R2.2
N$89
  Bottom 0.406: IC2.1 44.45,30.48 52.07,22.86 77.47,22.86 78.74,21.59 R3.2
N$90
  Bottom 0.406: IC2.2 43.18,29.84 51.44,21.59 67.94,21.59 68.58,20.95 R4.2
N$91
  Bottom 0.406: IC2.3 41.91,29.21 50.8,20.32 60.33,20.32 R5.2
N$92
  Bottom 0.406: IC2.4 40.64,27.94 48.26,20.32 R6.2
N$93
  Bottom 0.406: R7.2 38.1,26.67 39.37,27.94 IC2.5
N$94
  Bottom 0.406: IC2.6 38.1,29.21 29.21,20.32 R8.2
N$95
  Bottom 0.406: IC2.7 36.83,29.84 29.84,22.86 28.57,22.86 26.67,20.95 R9.2
N$96
  Bottom 0.406: R2.1 88.9,17.14 92.08,17.14 92.71,17.78 LED1.A
N$97
  Bottom 0.406: R3.1 78.74,17.14 81.92,17.14 82.55,17.78 LED2.A
N$98
  Bottom 0.406: R4.1 68.58,17.14 71.12,17.14 71.75,17.78 LED3.A
N$99
  Bottom 0.406: R5.1 60.33,17.14 61.59,17.14 62.23,17.78 LED4.A
N$100
  Bottom 0.406: R6.1 48.26,17.14 51.44,17.14 52.07,17.78 LED5.A
N$101
  Bottom 0.406: R7.1 38.1,17.14 41.27,17.14 41.91,17.78 LED6.A
N$102
  Bottom 0.406: R8.1 29.21,17.14 31.11,17.14 31.75,17.78 LED7.A
N$103
  Bottom 0.406: R9.1 26.67,17.14 24.77,17.14 24.13,17.78 LED8.A
N$104
  Bottom 0.406: IC1.2 82.55,40.32 86.68,40.32 88.9,42.55 88.9,44.45 JP2.1
N$105
  Bottom 0.406: R16.2 100.33,25.4 P2.1
N$106  (via drill 0.6)
  Top 0.406: v104.14,17.78 101.6,20.32 78.74,20.32 72.39,26.67 IC1.15
  Bottom 0.406: 105.41,19.05 IC11.10 | 105.41,19.05 106.68,19.05 IC11.11 | 105.41,19.05 105.41,17.78 v104.14,17.78
N$107  (via drill 0.6)
  Top 0.406: v96.52,22.23 79.38,22.23 74.93,26.67 IC1.16
  Bottom 0.406: R18.2 99.06,22.23 v96.52,22.23
N$108  (1 unrouted)
  Top 0.406: S4.2 59.69,10.16 59.69,22.86 64.77,27.94 IC1.12
  Bottom 0.406: S5.4 S4.2
N$109
  Bottom 0.406: P2.3 109.22,30.48 109.22,39.37 127,39.37 127,17.78 119.69,17.78 IC10.3
N$110
  Bottom 0.406: R14.1 124.46,14.92 121.92,14.92 | 121.92,14.92 R15.1 | IC10.4 119.69,15.56 120.33,14.92 121.92,14.92
N$111  (via drill 0.6)
  Top 0.406: v38.1,45.72 33.02,50.8 16.51,50.8 13.34,53.98 13.34,64.77 14.61,66.04 JP3.4
  Bottom 0.406: JP1.4 IC1.19 82.55,29.84 81.28,31.11 59.05,31.11 44.45,45.72 v38.1,45.72 IC2.11 | IC8.3 87.63,64.77 86.68,65.72 84.14,65.72 82.55,64.14 82.55,62.23 81.92,61.59 74.93,61.59 IC7.3 74.93,64.77 73.98,65.72 71.44,65.72 69.85,64.14 69.85,62.23 69.22,61.59 62.23,61.59 IC6.3 62.23,64.77 61.28,65.72 58.74,65.72 57.15,64.14 57.15,62.23 56.52,61.59 49.53,61.59 IC5.3 49.53,64.77 48.58,65.72 46.04,65.72 44.45,64.14 44.45,62.23 43.81,61.59 36.83,61.59 IC4.3 36.83,64.77 35.88,65.72 33.34,65.72 31.75,64.14 31.75,62.23 31.11,61.59 24.13,61.59 IC3.3 24.13,64.77 23.18,65.72 21.59,66.04 JP3.4
N$115
  Bottom 0.406: JP4.1 R19.1
N$116
  Bottom 0.406: 113.03,16.51 113.03,16.28 R13.2 | R18.1 99.06,19.68 101.19,19.68 C4.1
  Bottom 0.61: IC11.1 113.03,16.51 112.39,17.78 109.22,17.78 IC11.13 109.22,22.54 101.6,22.54 C4.1
N$117  (via drill 0.6)
  Top 0.406: v101.6,12.7 80.01,12.7 77.47,15.24 77.47,19.05 69.85,26.67 IC1.14
  Bottom 0.406: R19.2 102.87,12.7 v101.6,12.7
N$118  (via drill 0.6)
  Top 0.406: v13.34,48.26 13.34,50.16 LED10.A
  Bottom 0.406: R20.2 v13.34,48.26

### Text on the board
tPlace: Pulse generator (2016)
tNames: GND | Cl | S | D | +5V | power | frequency | piezo | bright | +5V | GND | ICSP | C | D | G | + | Vpp | level | Sync | G | G | Out
bNames: piezo | +5V | S | G | G | O
panel: Square Wave Frequency Generator | Pwr On | OUTPUT FREQUENCY / LEVEL | On | TUNING | Off | OUTPUT LEVEL | COARSE | TUNING | OUTPUT | HIGH | FINE | SWEEP | MAN | F1 | F2 | F3 | F4 | LEVEL | RANGE | F3-F4 | F3-F4 | OUTPUT | bcs 2016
